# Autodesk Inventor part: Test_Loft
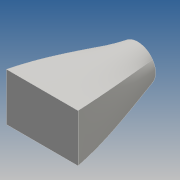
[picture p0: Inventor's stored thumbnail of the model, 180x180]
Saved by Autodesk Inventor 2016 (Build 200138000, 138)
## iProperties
Created: 2015-09
Part Number: Test_Loft
Material: Generic
Document SubType Name: Modeling
Designer: julian.chica
Density: 1 g/cm^3
Appearance: Default
Author: julian.chica
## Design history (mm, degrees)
sketch "Sketch1"
  geometry: L1 (15, 10)-(-15, 10); L2 (-15, 10)-(-15, -10); L3 (-15, -10)-(15, -10); L4 (15, -10)-(15, 10); L5 (15, 10)-(-15, -10); L6 (-15, 10)-(15, -10); 1 further point
  constraints: 12 end point, 2 midpoint, 2 parallel, 1 horizontal, 1 perpendicular
  dimensions: "d0" = 30 distance of L3.end L2.end; "d1" = 20 distance of L2.end L1.end
sketch "Sketch2"
  geometry: L1 (0, 0)-(0, 40)
  constraints: 2 end point, 1 vertical
  dimensions: "d2" = 40 distance of L1.start L1.end
workplane "Work Plane1"
sketch "Sketch3"
  geometry: C1 r 7.5 at (0, 0); 1 further point
  constraints: 1 centre point, 1 coincident
  dimensions: "d3" = 15 diameter of C1
loft "Loft1" sketch "Sketch3" dims "d4" = 0, "d5" = 90 deg, "d6" = 0, "d7" = 90 deg, "d8" = 0, "d9" = 90 deg, "d10" = 0, "d11" = 0, "d12" = 60, "d13" = 10, "d14" = 40, "d15" = 10, "d16" = 17.67146, "d17" = 10, "d18" = 20.08577, "d19" = 5.02144, "d20" = 40, "d21" = 11.22289
body "Solid1"
